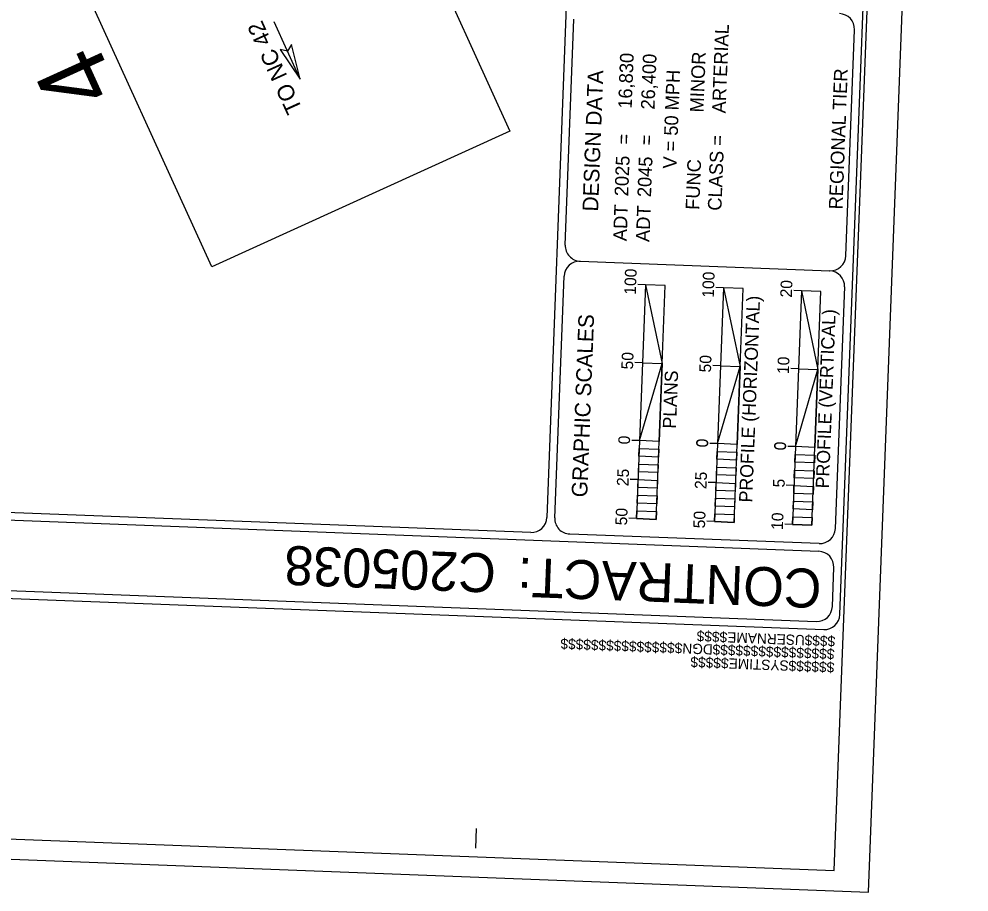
# Model space of a CAD drawing. Extents: x 2094564 to 2100382, y 679033 to 692366.
# Drawn here: x 2097338 to 2100382, y 682079 to 684877 of the extents above; entities that cross this region are included whole.
import ezdxf

# ---------------------------------------------------------------- set-up
doc = ezdxf.new("R2010")
doc.units = 0
for name, color, linetype in [('Exist Horizontal Alignment', 7, 'Continuous'), ('Pattern 17', 7, 'Continuous'), ('Prop Horizontal Alignment', 7, 'Continuous'), ('Prop Horizontal Alignment Direction Label', 7, 'Continuous'), ('Prop Horizontal Alignment Tick Label', 7, 'Continuous'), ('Prop Horizontal Alignment Tick Large', 7, 'Continuous'), ('Scratch_Level_0', 7, 'Continuous')]:
    doc.layers.add(name, color=color, linetype=linetype)

msp = doc.modelspace()

# ---------------------------------------------------------------- linework, layer by layer
at = {"layer": 'Exist Horizontal Alignment'}
msp.add_lwpolyline([(2098174.9, 684778.6), (2098239.3, 684684.4), (2098210.5, 684795.5), (2098198.3, 684774.1)], close=True, dxfattribs=at)
at = {"layer": 'Pattern 17'}
msp.add_lwpolyline([(2098911.1, 684517.1), (2097955.4, 684082.2), (2097499.9, 685083.3), (2097417, 685265.4), (2097440.9, 685276.3), (2097563.6, 685332.1), (2097512.9, 685443.5), (2098323.2, 685809.3)], close=True, dxfattribs=at)
at = {"layer": 'Prop Horizontal Alignment'}
msp.add_line((2098239.3, 684684.4), (2098155.9, 684867.8), dxfattribs=at)
at = {"layer": 'Prop Horizontal Alignment Direction Label'}
for p, q in [((2099030, 683278.9), (2099302.1, 690373.6)), ((2099088.6, 684152.3), (2099116.3, 684876.7)), ((2099136.6, 684100.4), (2099936, 684069.7)), ((2099055, 683277.9), (2099084.7, 684052.3)), ((2099345.8, 684024.8), (2099317.1, 683275.4)), ((2099345.8, 684024.8), (2099320.8, 684025.8)), ((2099408.3, 684022.4), (2099345.8, 684024.8)), ((2099379.5, 683273), (2099408.3, 684022.4)), ((2099595.6, 684015.2), (2099567, 683265.8)), ((2099595.6, 684015.2), (2099567, 683265.8)), ((2099595.6, 684015.2), (2099570.7, 684016.2)), ((2099595.6, 684015.2), (2099570.7, 684016.2)), ((2099658.1, 684012.8), (2099595.6, 684015.2)), ((2099629.4, 683263.4), (2099658.1, 684012.8)), ((2099845.5, 684005.6), (2099816.8, 683256.3)), ((2099845.5, 684005.6), (2099816.8, 683256.3)), ((2099845.5, 684005.6), (2099816.8, 683256.3)), ((2099845.5, 684005.6), (2099820.5, 684006.6)), ((2099845.5, 684005.6), (2099820.5, 684006.6)), ((2099845.5, 684005.6), (2099820.5, 684006.6)), ((2099907.9, 684003.3), (2099845.5, 684005.6)), ((2099879.2, 683253.8), (2099907.9, 684003.3)), ((2099336.2, 683775), (2099311.3, 683775.9)), ((2099336.2, 683775), (2099398.7, 683772.6)), ((2099586.1, 683765.4), (2099561.1, 683766.4)), ((2099586.1, 683765.4), (2099561.1, 683766.4)), ((2099586.1, 683765.4), (2099648.5, 683763)), ((2099835.9, 683755.8), (2099810.9, 683756.8)), ((2099835.9, 683755.8), (2099810.9, 683756.8)), ((2099835.9, 683755.8), (2099810.9, 683756.8)), ((2099835.9, 683755.8), (2099898.4, 683753.4)), ((2099326.7, 683525.2), (2099301.7, 683526.1)), ((2099576.5, 683515.6), (2099551.6, 683516.6)), ((2099576.5, 683515.6), (2099551.6, 683516.6)), ((2099826.3, 683506), (2099801.4, 683507)), ((2099826.3, 683506), (2099801.4, 683507)), ((2099826.3, 683506), (2099801.4, 683507)), ((2099323.8, 683450.2), (2099386.2, 683447.8)), ((2099573.7, 683440.6), (2099636.1, 683438.3)), ((2099823.5, 683431.1), (2099885.9, 683428.7)), ((2098978.1, 683230.8), (2094806.2, 683390.8)), ((2099321.9, 683400.3), (2099296.9, 683401.2)), ((2099571.8, 683390.7), (2099546.7, 683391.6)), ((2099571.8, 683390.7), (2099546.7, 683391.6)), ((2099821.5, 683381.1), (2099796.6, 683382.1)), ((2099821.5, 683381.1), (2099796.6, 683382.1)), ((2099821.5, 683381.1), (2099796.6, 683382.1)), ((2099901.5, 683170.4), (2094805.2, 683365.8)), ((2099317.1, 683275.4), (2099292.2, 683276.3)), ((2099292.2, 683276.3), (2099292.2, 683276.3)), ((2099317.1, 683275.4), (2099379.5, 683273)), ((2099317.1, 683275.4), (2099317.1, 683275.4)), ((2099567, 683265.8), (2099541.9, 683266.7)), ((2099567, 683265.8), (2099541.9, 683266.7)), ((2099541.9, 683266.7), (2099541.9, 683266.7)), ((2099567, 683265.8), (2099629.4, 683263.4)), ((2099567, 683265.8), (2099567, 683265.8)), ((2099567, 683265.8), (2099567, 683265.8)), ((2099816.8, 683256.3), (2099791.7, 683257.2)), ((2099816.8, 683256.3), (2099791.7, 683257.2)), ((2099816.8, 683256.3), (2099791.7, 683257.2)), ((2099791.7, 683257.2), (2099791.7, 683257.2)), ((2099816.8, 683256.3), (2099879.2, 683253.8)), ((2099816.8, 683256.3), (2099816.8, 683256.3)), ((2099816.8, 683256.3), (2099816.8, 683256.3)), ((2099816.8, 683256.3), (2099816.8, 683256.3)), ((2099902.5, 683195.4), (2099103, 683226)), ((2099966.9, 682917.7), (2099966.9, 682917.7)), ((2099966.9, 682917.7), (2099966.9, 682917.7)), ((2099966.9, 682917.7), (2099966.9, 682917.7)), ((2099966.9, 682917.7), (2099966.9, 682917.7)), ((2098801.8, 682219.3), (2098804.1, 682281.8)), ((2098801.8, 682219.3), (2098804.1, 682281.8))]:
    msp.add_line(p, q, dxfattribs=at)
for points in [[(2099968.8, 682967.7), (2100252.4, 690362.2)], [(2099987.9, 684117.8), (2100015.6, 684842.2)], [(2099954.4, 683243.4), (2099984, 684017.8)], [(2094796.6, 683141.1), (2099892.9, 682945.6)], [(2094770.7, 683117), (2099916.9, 682919.6)], [(2094770.7, 683117), (2099916.9, 682919.6)], [(2099944.7, 682993.5), (2099949.5, 683118.5)]]:
    msp.add_lwpolyline(points, dxfattribs=at)
for points in [[(2099345.8, 684024.8), (2099398.7, 683772.6), (2099408.3, 684022.4)], [(2099595.6, 684015.2), (2099648.5, 683763), (2099658.1, 684012.8)], [(2099845.5, 684005.6), (2099898.4, 683753.4), (2099907.9, 684003.3)], [(2099326.7, 683525.2), (2099398.7, 683772.6), (2099389.2, 683522.8)], [(2099576.5, 683515.6), (2099648.5, 683763), (2099639, 683513.2)], [(2099826.3, 683506), (2099898.4, 683753.4), (2099888.7, 683503.6)], [(2099324.7, 683475.2), (2099325.7, 683500.2), (2099388.2, 683497.8), (2099387.2, 683472.8)], [(2099574.6, 683465.6), (2099575.5, 683490.6), (2099638, 683488.2), (2099637, 683463.2)], [(2099824.4, 683456), (2099825.3, 683481), (2099887.8, 683478.6), (2099886.8, 683453.7)], [(2099322.9, 683425.2), (2099323.8, 683450.2), (2099386.2, 683447.8), (2099385.3, 683422.9)], [(2099572.7, 683415.7), (2099573.7, 683440.6), (2099636.1, 683438.3), (2099635.1, 683413.3)], [(2099822.5, 683406.1), (2099823.5, 683431.1), (2099885.9, 683428.7), (2099884.9, 683403.7)], [(2099321, 683375.3), (2099321.9, 683400.3), (2099384.3, 683397.9), (2099383.4, 683372.9)], [(2099570.7, 683365.7), (2099571.8, 683390.7), (2099634.1, 683388.3), (2099633.2, 683363.3)], [(2099820.5, 683356.1), (2099821.5, 683381.1), (2099884, 683378.7), (2099883, 683353.7)], [(2099319, 683325.3), (2099320, 683350.3), (2099382.5, 683347.9), (2099381.5, 683323)], [(2099568.8, 683315.7), (2099569.8, 683340.7), (2099632.3, 683338.4), (2099631.3, 683313.3)], [(2099818.6, 683306.2), (2099819.6, 683331.1), (2099882, 683328.7), (2099881.1, 683303.8)], [(2099317.1, 683275.4), (2099318, 683300.3), (2099380.5, 683297.9), (2099379.5, 683273)], [(2099567, 683265.8), (2099567.9, 683290.8), (2099630.3, 683288.4), (2099629.4, 683263.4)], [(2099816.8, 683256.3), (2099817.7, 683281.2), (2099880.2, 683278.8), (2099879.2, 683253.8)]]:
    msp.add_lwpolyline(points, close=True, dxfattribs=at)
for centre, start, end in [((2099965.5, 684844.2), 357.8037, 87.8037), ((2099138.3, 684150.4), 177.8037, 267.8037), ((2099937.7, 684119.7), 267.8037, 357.8037), ((2099134.4, 684050.5), 87.8037, 177.8037), ((2099933.8, 684019.8), 357.8037, 87.8037), ((2098979.8, 683280.8), 267.8037, 357.8037), ((2099104.7, 683276), 177.8037, 267.8037), ((2099904.1, 683245.4), 267.8037, 357.8037), ((2099899.3, 683120.5), 357.8037, 87.8037), ((2099894.6, 682995.5), 267.8037, 357.8037), ((2099918.6, 682969.6), 267.8037, 357.8037)]:
    msp.add_arc(centre, 50, start, end, dxfattribs=at)
at = {"layer": 'Prop Horizontal Alignment Tick Label'}
msp.add_lwpolyline([(2099950.1, 682147.8), (2100269.5, 690474.2), (2094997.8, 690676.3), (2094678.5, 682349.9)], close=True, dxfattribs=at)
at = {"layer": 'Prop Horizontal Alignment Tick Large'}
msp.add_lwpolyline([(2094886.5, 690703.1), (2094563.9, 682289.3), (2100059.8, 682078.5), (2100382.4, 690492.3)], close=True, dxfattribs=at)
at = {"layer": 'Scratch_Level_0'}
for p, q in [((2099345.8, 684024.9), (2099320.8, 684025.8)), ((2099336.2, 683775.1), (2099311.3, 683776)), ((2099321.9, 683400.3), (2099296.9, 683401.3)), ((2099317, 683275.4), (2099292.1, 683276.4)), ((2099966.9, 682917.8), (2099966.9, 682917.8))]:
    msp.add_line(p, q, dxfattribs=at)

# ---------------------------------------------------------------- texts
at = {"layer": 'Prop Horizontal Alignment Direction Label'}
for s, height, rotation, p in [('4', 225.9, 114.4674, (2097655.2, 684650.5)), ('DESIGN DATA', 49.998, 87.8037, (2099193.5, 684259.1)), ('PROFILE (HORIZONTAL)', 42.498, 87.8037, (2099687.6, 683326.4)), ('GRAPHIC SCALES', 49.998, 87.8037, (2099158.6, 683343)), ('PROFILE (VERTICAL)', 42.498, 87.8037, (2099933.3, 683371.6)), ('PLANS', 42.5, 87.8037, (2099443.3, 683563.2)), ('0', 37.5, 87.8037, (2099295.5, 683512.6)), ('0', 37.5, 87.8037, (2099545.2, 683503)), ('0', 37.5, 87.8037, (2099546, 683503)), ('0', 37.5, 87.8037, (2099795, 683493.5)), ('0', 37.5, 87.8037, (2099795.8, 683493.4)), ('0', 37.5, 87.8037, (2099795.8, 683493.4)), ('C205038', 125, 177.8037, (2098868.5, 683162.5)), ('CONTRACT:', 125, 177.8037, (2099912, 683113)), ('$$$$$$$$$$$$$$$$DGN$$$$$$$$$$$$$$$$', 32.812, 177.8037, (2099952, 682857.2)), ('$$$$USERNAME$$$$', 32.812, 177.8037, (2099954.4, 682898.1)), ('$$$$$$SYSTIME$$$$$', 32.812, 177.8037, (2099951.6, 682814.6))]:
    msp.add_text(s, height=height, rotation=rotation, dxfattribs=at).set_placement(p)
at = {"layer": 'Scratch_Level_0'}
for s, height, rotation, p in [('TO NC 42', 52.56, 114.4674, (2098246.8, 684587.4)), ('ARTERIAL', 43.75, 87.8037, (2099602.3, 684573.8)), ('16,830', 43.75, 87.8037, (2099301.3, 684588.6)), ('26,400', 43.75, 87.8037, (2099374.4, 684585.8)), ('MINOR ', 43.75, 87.8037, (2099531.3, 684576.5)), ('REGIONAL TIER', 43.75, 87.8037, (2099976.8, 684265.8)), ('V = 50 MPH', 43.75, 87.8037, (2099444.8, 684396.3)), ('=', 43.8, 87.8037, (2099296.7, 684473.7)), ('=', 43.8, 87.8037, (2099369.8, 684470.9)), ('CLASS =', 43.75, 87.8037, (2099588.8, 684261.7)), ('2025', 43.75, 87.8037, (2099290, 684307.9)), ('2045', 43.75, 87.8037, (2099363.2, 684305)), ('FUNC ', 43.75, 87.8037, (2099517.8, 684264.4)), ('ADT', 43.75, 87.8037, (2099285.1, 684164.2)), ('ADT', 43.75, 87.8037, (2099358.2, 684161.4)), ('100', 37.5, 87.8037, (2099314.5, 683992.3)), ('100', 37.5, 87.8037, (2099564.3, 683982.7)), ('20', 37.5, 87.8037, (2099814.6, 683983.5)), ('50', 37.5, 87.8037, (2099305.4, 683752.8)), ('50', 37.5, 87.8037, (2099555.2, 683743.2)), ('10', 37.5, 87.8037, (2099805.1, 683738.1)), ('25', 37.5, 87.8037, (2099291, 683378.8)), ('25', 37.5, 87.8037, (2099540.8, 683369.3)), ('5', 37.5, 87.8037, (2099791.2, 683374.5)), ('50', 37.5, 87.8037, (2099286.2, 683253.2)), ('50', 37.5, 87.8037, (2099536, 683243.6)), ('10', 37.5, 87.8037, (2099785.9, 683238.5))]:
    msp.add_text(s, height=height, rotation=rotation, dxfattribs=at).set_placement(p)

doc.saveas('drawing.dxf')
